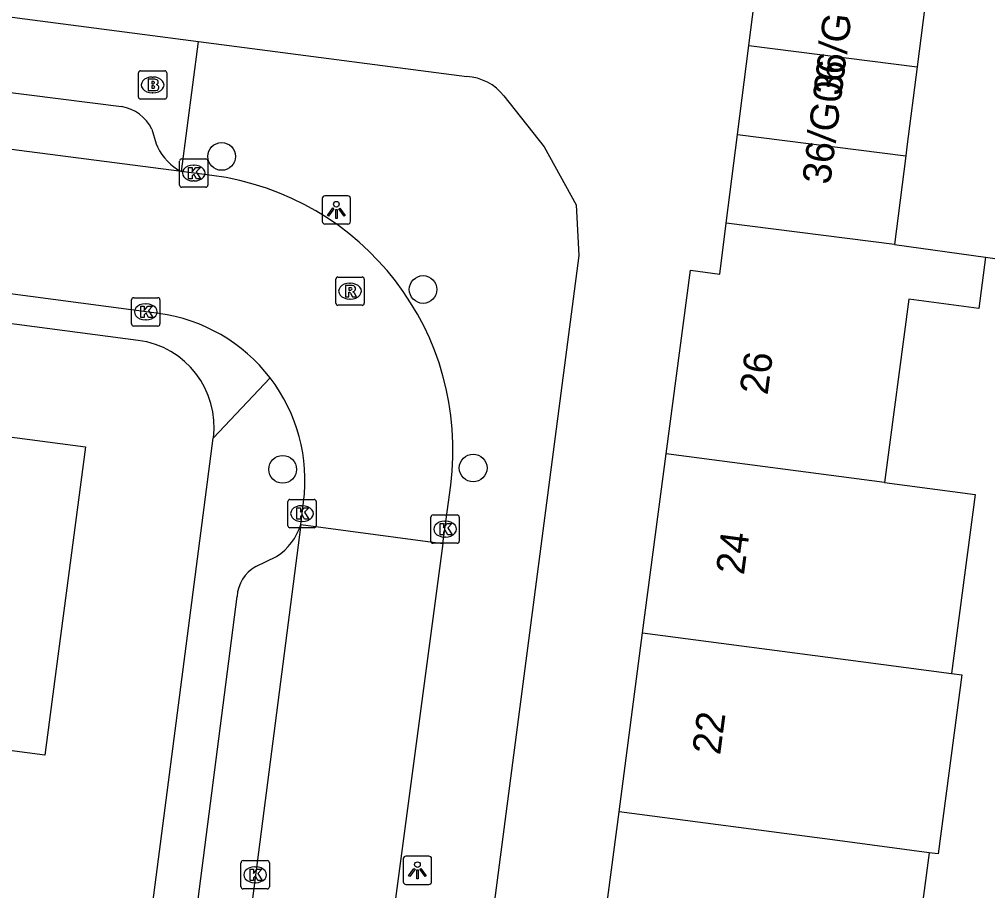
# Model space of a CAD drawing. Extents: x 162186 to 163152, y 385513 to 386513.
# Drawn here: x 162510.63 to 162544.83, y 386223.73 to 386254.5 of the extents above; entities that cross this region are included whole.
import ezdxf

# ---------------------------------------------------------------- set-up
doc = ezdxf.new("R2010")
doc.units = 0
for name, color, linetype in [('IMGEO_Boom', 7, 'Continuous'), ('IMGEO_Brandkraan', 7, 'Continuous'), ('IMGEO_Kolk', 7, 'Continuous'), ('IMGEO_Lichtpunt', 7, 'Continuous'), ('IMGEO_Muur', 7, 'Continuous'), ('IMGEO_Pand', 7, 'Continuous'), ('IMGEO_Pand_nummerreeks', 7, 'Continuous'), ('IMGEO_Rijbaan_lokaal_open', 7, 'Continuous'), ('IMGEO_Rioolput', 7, 'Continuous'), ('IMGEO_Voetpad_open', 7, 'Continuous')]:
    doc.layers.add(name, color=color, linetype=linetype)

msp = doc.modelspace()

# ---------------------------------------------------------------- linework, layer by layer
at = {"layer": 'IMGEO_Boom'}
for centre in [(162517.778, 386249.657), (162524.891, 386244.959), (162519.931, 386238.608), (162526.659, 386238.655)]:
    msp.add_circle(centre, 0.489, dxfattribs=at)
at = {"layer": 'IMGEO_Brandkraan'}
for p, q in [((162514.914, 386252.681), (162515.766, 386252.681)), ((162514.839, 386251.755), (162514.839, 386252.607)), ((162515.327, 386252.461), (162515.352, 386252.461)), ((162515.84, 386252.607), (162515.84, 386251.755)), ((162515.766, 386251.681), (162514.914, 386251.681)), ((162515.35, 386251.901), (162515.325, 386251.901))]:
    msp.add_line(p, q, dxfattribs=at)
for points in [[(162514.914, 386252.681), (162515.766, 386252.681)], [(162514.839, 386251.755), (162514.839, 386252.607)], [(162515.187, 386252.381), (162515.187, 386251.981), (162515.4, 386251.981)], [(162515.418, 386252.381), (162515.187, 386252.381)], [(162515.84, 386252.607), (162515.84, 386251.755)], [(162515.366, 386252.3), (162515.312, 386252.3), (162515.312, 386252.224)], [(162515.312, 386252.224), (162515.365, 386252.224)], [(162515.374, 386252.148), (162515.312, 386252.148), (162515.312, 386252.067)], [(162515.312, 386252.067), (162515.374, 386252.067)], [(162515.766, 386251.681), (162514.914, 386251.681)]]:
    msp.add_lwpolyline(points, dxfattribs=at)
for centre, radius, start, end in [((162514.916, 386252.605), 0.0765, 91.552, 178.448), ((162514.916, 386252.605), 0.0765, 91.552, 178.448), ((162515.764, 386252.605), 0.0765, 1.552, 88.448), ((162515.764, 386252.605), 0.0765, 1.552, 88.448), ((162515.422, 386252.236), 0.145, 59.4692, 91.5367), ((162515.447, 386252.283), 0.0922, 285.5137, 58.1501), ((162515.367, 386252.262), 0.0379, 267.8285, 90.9355), ((162515.375, 386252.107), 0.0404, 269.8759, 90.5077), ((162515.406, 386252.232), 0.251, 268.6676, 293.5347), ((162515.452, 386252.091), 0.105, 301.3115, 78.989), ((162514.916, 386251.757), 0.0765, 181.552, 268.448), ((162514.916, 386251.757), 0.0765, 181.552, 268.448), ((162515.764, 386251.757), 0.0765, 271.552, 358.448), ((162515.764, 386251.757), 0.0765, 271.552, 358.448)]:
    msp.add_arc(centre, radius, start, end, dxfattribs=at)
for centre, major_axis, ratio, start_param, end_param in [((162515.326, 386252.181), (-0.387, 0.002), 0.722429, 4.712389, 7.853982), ((162515.351, 386252.181), (-0.39, 0.002), 0.717154, 1.570796, 4.712389)]:
    msp.add_ellipse(centre, major_axis=major_axis, ratio=ratio, start_param=start_param, end_param=end_param, dxfattribs=at)
at = {"layer": 'IMGEO_Kolk'}
for p, q in [((162516.29, 386248.644), (162516.29, 386249.496)), ((162516.365, 386249.57), (162517.217, 386249.57)), ((162516.778, 386249.35), (162516.803, 386249.35)), ((162517.291, 386249.496), (162517.291, 386248.644)), ((162517.217, 386248.57), (162516.365, 386248.57)), ((162516.801, 386248.79), (162516.776, 386248.79)), ((162514.598, 386243.743), (162514.598, 386244.595)), ((162514.673, 386244.669), (162515.525, 386244.669)), ((162515.599, 386244.595), (162515.599, 386243.743)), ((162515.086, 386244.449), (162515.111, 386244.449)), ((162515.109, 386243.889), (162515.084, 386243.889)), ((162515.525, 386243.669), (162514.673, 386243.669)), ((162520.114, 386236.619), (162520.114, 386237.471)), ((162520.189, 386237.545), (162521.041, 386237.545)), ((162520.602, 386237.325), (162520.627, 386237.325)), ((162521.115, 386237.471), (162521.115, 386236.619)), ((162525.243, 386236.997), (162526.095, 386236.997)), ((162520.625, 386236.765), (162520.6, 386236.765)), ((162525.168, 386236.071), (162525.168, 386236.923)), ((162525.656, 386236.777), (162525.681, 386236.777)), ((162526.169, 386236.923), (162526.169, 386236.071)), ((162521.041, 386236.545), (162520.189, 386236.545)), ((162526.095, 386235.997), (162525.243, 386235.997)), ((162525.679, 386236.217), (162525.654, 386236.217)), ((162518.46, 386223.868), (162518.46, 386224.72)), ((162518.535, 386224.794), (162519.387, 386224.794)), ((162519.461, 386224.72), (162519.461, 386223.868)), ((162518.948, 386224.574), (162518.973, 386224.574)), ((162518.971, 386224.014), (162518.946, 386224.014)), ((162519.387, 386223.794), (162518.535, 386223.794))]:
    msp.add_line(p, q, dxfattribs=at)
for points in [[(162516.29, 386248.644), (162516.29, 386249.496)], [(162516.365, 386249.57), (162517.217, 386249.57)], [(162516.611, 386249.27), (162516.734, 386249.27), (162516.734, 386249.119), (162516.864, 386249.27), (162517.028, 386249.27), (162516.882, 386249.119), (162517.035, 386248.87), (162516.883, 386248.87), (162516.798, 386249.034), (162516.734, 386248.967), (162516.734, 386248.87), (162516.611, 386248.87), (162516.611, 386249.27)], [(162517.291, 386249.496), (162517.291, 386248.644)], [(162517.217, 386248.57), (162516.365, 386248.57)], [(162514.598, 386243.743), (162514.598, 386244.595)], [(162514.673, 386244.669), (162515.525, 386244.669)], [(162515.599, 386244.595), (162515.599, 386243.743)], [(162514.919, 386244.369), (162515.042, 386244.369), (162515.042, 386244.218), (162515.172, 386244.369), (162515.336, 386244.369), (162515.19, 386244.218), (162515.343, 386243.969), (162515.191, 386243.969), (162515.106, 386244.133), (162515.042, 386244.066), (162515.042, 386243.969), (162514.919, 386243.969), (162514.919, 386244.369)], [(162515.525, 386243.669), (162514.673, 386243.669)], [(162520.114, 386236.619), (162520.114, 386237.471)], [(162520.189, 386237.545), (162521.041, 386237.545)], [(162521.115, 386237.471), (162521.115, 386236.619)], [(162520.435, 386237.245), (162520.558, 386237.245), (162520.558, 386237.094), (162520.688, 386237.245), (162520.852, 386237.245), (162520.706, 386237.094), (162520.859, 386236.845), (162520.707, 386236.845), (162520.622, 386237.009), (162520.558, 386236.942), (162520.558, 386236.845), (162520.435, 386236.845), (162520.435, 386237.245)], [(162525.243, 386236.997), (162526.095, 386236.997)], [(162525.168, 386236.071), (162525.168, 386236.923)], [(162525.489, 386236.697), (162525.612, 386236.697), (162525.612, 386236.546), (162525.742, 386236.697), (162525.906, 386236.697), (162525.76, 386236.546), (162525.913, 386236.297), (162525.761, 386236.297), (162525.676, 386236.461), (162525.612, 386236.394), (162525.612, 386236.297), (162525.489, 386236.297), (162525.489, 386236.697)], [(162526.169, 386236.923), (162526.169, 386236.071)], [(162521.041, 386236.545), (162520.189, 386236.545)], [(162526.095, 386235.997), (162525.243, 386235.997)], [(162518.46, 386223.868), (162518.46, 386224.72)], [(162518.535, 386224.794), (162519.387, 386224.794)], [(162519.461, 386224.72), (162519.461, 386223.868)], [(162518.781, 386224.494), (162518.904, 386224.494), (162518.904, 386224.343), (162519.034, 386224.494), (162519.198, 386224.494), (162519.052, 386224.343), (162519.205, 386224.094), (162519.053, 386224.094), (162518.968, 386224.258), (162518.904, 386224.191), (162518.904, 386224.094), (162518.781, 386224.094), (162518.781, 386224.494)], [(162519.387, 386223.794), (162518.535, 386223.794)]]:
    msp.add_lwpolyline(points, dxfattribs=at)
for centre, start, end in [((162516.367, 386249.494), 91.552, 178.448), ((162516.367, 386249.494), 91.552, 178.448), ((162517.215, 386249.494), 1.552, 88.448), ((162517.215, 386249.494), 1.552, 88.448), ((162516.367, 386248.646), 181.552, 268.448), ((162516.367, 386248.646), 181.552, 268.448), ((162517.215, 386248.646), 271.552, 358.448), ((162517.215, 386248.646), 271.552, 358.448), ((162514.675, 386244.593), 91.552, 178.448), ((162514.675, 386244.593), 91.552, 178.448), ((162515.523, 386244.593), 1.552, 88.448), ((162515.523, 386244.593), 1.552, 88.448), ((162514.675, 386243.745), 181.552, 268.448), ((162514.675, 386243.745), 181.552, 268.448), ((162515.523, 386243.745), 271.552, 358.448), ((162515.523, 386243.745), 271.552, 358.448), ((162520.191, 386237.469), 91.552, 178.448), ((162520.191, 386237.469), 91.552, 178.448), ((162521.039, 386237.469), 1.552, 88.448), ((162521.039, 386237.469), 1.552, 88.448), ((162525.245, 386236.921), 91.552, 178.448), ((162525.245, 386236.921), 91.552, 178.448), ((162526.093, 386236.921), 1.552, 88.448), ((162526.093, 386236.921), 1.552, 88.448), ((162520.191, 386236.621), 181.552, 268.448), ((162520.191, 386236.621), 181.552, 268.448), ((162521.039, 386236.621), 271.552, 358.448), ((162521.039, 386236.621), 271.552, 358.448), ((162525.245, 386236.073), 181.552, 268.448), ((162525.245, 386236.073), 181.552, 268.448), ((162526.093, 386236.073), 271.552, 358.448), ((162526.093, 386236.073), 271.552, 358.448), ((162518.537, 386224.718), 91.552, 178.448), ((162518.537, 386224.718), 91.552, 178.448), ((162519.385, 386224.718), 1.552, 88.448), ((162519.385, 386224.718), 1.552, 88.448), ((162518.537, 386223.87), 181.552, 268.448), ((162518.537, 386223.87), 181.552, 268.448), ((162519.385, 386223.87), 271.552, 358.448), ((162519.385, 386223.87), 271.552, 358.448)]:
    msp.add_arc(centre, 0.0765, start, end, dxfattribs=at)
for centre, major_axis, ratio, start_param, end_param in [((162516.777, 386249.07), (-0.387, 0.002), 0.722429, 4.712389, 7.853982), ((162516.802, 386249.07), (-0.39, 0.002), 0.717154, 1.570796, 4.712389), ((162515.085, 386244.169), (-0.387, 0.002), 0.722429, 4.712389, 7.853982), ((162515.11, 386244.169), (-0.39, 0.002), 0.717154, 1.570796, 4.712389), ((162520.601, 386237.045), (-0.387, 0.002), 0.722429, 4.712389, 7.853982), ((162520.626, 386237.045), (-0.39, 0.002), 0.717154, 1.570796, 4.712389), ((162525.655, 386236.497), (-0.387, 0.002), 0.722429, 4.712389, 7.853982), ((162525.68, 386236.497), (-0.39, 0.002), 0.717154, 1.570796, 4.712389), ((162518.947, 386224.294), (-0.387, 0.002), 0.722429, 4.712389, 7.853982), ((162518.972, 386224.294), (-0.39, 0.002), 0.717154, 1.570796, 4.712389)]:
    msp.add_ellipse(centre, major_axis=major_axis, ratio=ratio, start_param=start_param, end_param=end_param, dxfattribs=at)
at = {"layer": 'IMGEO_Lichtpunt'}
for p, q in [((162522.232, 386248.268), (162521.424, 386248.268)), ((162522.232, 386248.268), (162521.424, 386248.268)), ((162521.33, 386248.173), (162521.33, 386247.366)), ((162521.33, 386248.173), (162521.33, 386247.366)), ((162522.326, 386247.366), (162522.326, 386248.173)), ((162522.326, 386247.366), (162522.326, 386248.173)), ((162521.424, 386247.272), (162522.232, 386247.272)), ((162521.424, 386247.272), (162522.232, 386247.272)), ((162524.193, 386224.855), (162524.193, 386224.048)), ((162524.193, 386224.855), (162524.193, 386224.048)), ((162525.095, 386224.95), (162524.287, 386224.95)), ((162525.095, 386224.95), (162524.287, 386224.95)), ((162525.189, 386224.048), (162525.189, 386224.855)), ((162525.189, 386224.048), (162525.189, 386224.855)), ((162524.287, 386223.954), (162525.095, 386223.954)), ((162524.287, 386223.954), (162525.095, 386223.954))]:
    msp.add_line(p, q, dxfattribs=at)
for points in [[(162521.704, 386247.837), (162521.743, 386247.809), (162521.555, 386247.547), (162521.517, 386247.574), (162521.704, 386247.837)], [(162521.806, 386247.789), (162521.853, 386247.789), (162521.853, 386247.467), (162521.806, 386247.467), (162521.806, 386247.789)], [(162521.916, 386247.809), (162521.954, 386247.836), (162522.141, 386247.574), (162522.102, 386247.546), (162521.916, 386247.809)], [(162524.567, 386224.519), (162524.606, 386224.491), (162524.418, 386224.229), (162524.38, 386224.256), (162524.567, 386224.519)], [(162524.669, 386224.471), (162524.716, 386224.471), (162524.716, 386224.149), (162524.669, 386224.149), (162524.669, 386224.471)], [(162524.779, 386224.491), (162524.817, 386224.518), (162525.004, 386224.256), (162524.965, 386224.228), (162524.779, 386224.491)]]:
    msp.add_lwpolyline(points, dxfattribs=at)
for centre in [(162521.829, 386247.971), (162524.692, 386224.653)]:
    msp.add_circle(centre, 0.0994, dxfattribs=at)
for centre, start, end in [((162521.424, 386248.173), 90, 180), ((162521.424, 386248.173), 90, 180), ((162522.232, 386248.173), 0, 90), ((162522.232, 386248.173), 0, 90), ((162521.424, 386247.366), 180, 270), ((162521.424, 386247.366), 180, 270), ((162522.232, 386247.366), 270, 0), ((162522.232, 386247.366), 270, 360), ((162524.287, 386224.855), 90, 180), ((162524.287, 386224.855), 90, 180), ((162525.095, 386224.855), 0, 90), ((162525.095, 386224.855), 0, 90), ((162524.287, 386224.048), 180, 270), ((162524.287, 386224.048), 180, 270), ((162525.095, 386224.048), 270, 0), ((162525.095, 386224.048), 270, 360)]:
    msp.add_arc(centre, 0.0946, start, end, dxfattribs=at)
at = {"layer": 'IMGEO_Muur'}
msp.add_lwpolyline([(162544.758, 386246.095), (162549.689, 386245.409)], dxfattribs=at)
at = {"layer": 'IMGEO_Pand'}
for points in [[(162542.737, 386255.958), (162542.338, 386252.819)], [(162536.392, 386253.575), (162536.591, 386255.142)], [(162535.993, 386250.436), (162536.392, 386253.575)], [(162536.392, 386253.575), (162542.338, 386252.819)], [(162542.338, 386252.819), (162541.98, 386250), (162541.939, 386249.681)], [(162535.595, 386247.298), (162535.993, 386250.436)], [(162535.993, 386250.436), (162541.939, 386249.681)], [(162541.939, 386249.681), (162541.541, 386246.543)], [(162533.477, 386239.162), (162534.331, 386245.637), (162535.367, 386245.5), (162535.595, 386247.298)], [(162541.541, 386246.543), (162535.595, 386247.298)], [(162541.541, 386246.543), (162544.758, 386246.095)], [(162544.758, 386246.095), (162544.521, 386244.293), (162542.042, 386244.62), (162541.188, 386238.144)], [(162506.338, 386240.28), (162512.974, 386239.402), (162511.938, 386231.567), (162511.535, 386228.516), (162507.152, 386229.096), (162507.555, 386232.147), (162506.982, 386232.223), (162505.316, 386232.444)], [(162532.644, 386232.841), (162533.477, 386239.162)], [(162541.188, 386238.144), (162533.477, 386239.162)], [(162541.188, 386238.144), (162544.39, 386237.72), (162543.557, 386231.4)], [(162531.811, 386226.521), (162532.644, 386232.841)], [(162532.644, 386232.841), (162540.355, 386231.822), (162543.557, 386231.4)], [(162543.557, 386231.4), (162543.913, 386231.353), (162543.08, 386225.032), (162542.761, 386225.074)], [(162530.978, 386220.201), (162531.811, 386226.521)], [(162542.761, 386225.074), (162539.522, 386225.502), (162531.811, 386226.521)], [(162542.761, 386225.074), (162542.409, 386222.412), (162539.171, 386222.84), (162538.688, 386219.182)]]:
    msp.add_lwpolyline(points, dxfattribs=at)
at = {"layer": 'IMGEO_Rijbaan_lokaal_open'}
for points in [[(162516.358, 386249.125), (162509.618, 386250), (162500, 386251.249), (162452.282, 386257.493)], [(162515.557, 386244.109), (162500, 386246.174), (162474.386, 386249.54)], [(162517.434, 386248.985), (162516.358, 386249.125)], [(162544.758, 386246.095), (162549.689, 386245.409)], [(162525.592, 386235.986), (162525.867, 386238.045)], [(162520.569, 386236.666), (162520.67, 386237.453)], [(162520.569, 386236.666), (162514.746, 386191.574)], [(162520.569, 386236.666), (162525.592, 386235.986)], [(162525.592, 386235.986), (162519.686, 386191.776), (162519.542, 386190.566)]]:
    msp.add_lwpolyline(points, dxfattribs=at)
for centre, radius, start, end in [((162516.177, 386239.296), 9.77, 352.6451, 82.6079), ((162514.776, 386238.217), 5.944, 37.5352, 82.446), ((162514.779, 386238.218), 5.941, 352.602, 37.5453)]:
    msp.add_arc(centre, radius, start, end, dxfattribs=at)
at = {"layer": 'IMGEO_Rioolput'}
for p, q in [((162521.809, 386244.474), (162521.809, 386245.326)), ((162521.884, 386245.4), (162522.736, 386245.4)), ((162522.297, 386245.18), (162522.322, 386245.18)), ((162522.81, 386245.326), (162522.81, 386244.474)), ((162522.32, 386244.62), (162522.295, 386244.62)), ((162522.736, 386244.4), (162521.884, 386244.4))]:
    msp.add_line(p, q, dxfattribs=at)
for points in [[(162521.809, 386244.474), (162521.809, 386245.326)], [(162521.884, 386245.4), (162522.736, 386245.4)], [(162522.81, 386245.326), (162522.81, 386244.474)], [(162522.398, 386245.098), (162522.146, 386245.1), (162522.146, 386244.7)], [(162522.146, 386244.7), (162522.27, 386244.7), (162522.27, 386244.862), (162522.281, 386244.862)], [(162522.324, 386245.019), (162522.27, 386245.019), (162522.27, 386244.938)], [(162522.27, 386244.938), (162522.322, 386244.938)], [(162522.328, 386244.833), (162522.399, 386244.7), (162522.539, 386244.7), (162522.474, 386244.826)], [(162522.736, 386244.4), (162521.884, 386244.4)]]:
    msp.add_lwpolyline(points, dxfattribs=at)
for centre, radius, start, end in [((162521.886, 386245.324), 0.0765, 91.552, 178.448), ((162521.886, 386245.324), 0.0765, 91.552, 178.448), ((162522.734, 386245.324), 0.0765, 1.552, 88.448), ((162522.734, 386245.324), 0.0765, 1.552, 88.448), ((162522.28, 386244.809), 0.0533, 26.0293, 88.6989), ((162522.306, 386245.127), 0.19, 274.7715, 282.9687), ((162522.33, 386244.923), 0.0964, 77.0061, 93.1865), ((162522.344, 386244.98), 0.0378, 276.6634, 79.6772), ((162522.397, 386244.988), 0.109, 350.3612, 89.416), ((162522.395, 386244.988), 0.112, 277.5842, 350.9817), ((162522.379, 386244.773), 0.108, 29.5134, 73.7905), ((162521.886, 386244.476), 0.0765, 181.552, 268.448), ((162521.886, 386244.476), 0.0765, 181.552, 268.448), ((162522.734, 386244.476), 0.0765, 271.552, 358.448), ((162522.734, 386244.476), 0.0765, 271.552, 358.448)]:
    msp.add_arc(centre, radius, start, end, dxfattribs=at)
for centre, major_axis, ratio, start_param, end_param in [((162522.296, 386244.9), (-0.387, 0.002), 0.722429, 4.712389, 7.853982), ((162522.321, 386244.9), (-0.39, 0.002), 0.717154, 1.570796, 4.712389)]:
    msp.add_ellipse(centre, major_axis=major_axis, ratio=ratio, start_param=start_param, end_param=end_param, dxfattribs=at)
at = {"layer": 'IMGEO_Voetpad_open'}
for points in [[(162407.034, 386268.116), (162500, 386255.941), (162516.96, 386253.72)], [(162477.472, 386256.096), (162482.084, 386255.488), (162514.241, 386251.416)], [(162516.358, 386249.125), (162516.96, 386253.72)], [(162516.96, 386253.72), (162526.433, 386252.479)], [(162527.746, 386251.794), (162529.167, 386250), (162530.299, 386247.954), (162530.386, 386246.165), (162518.722, 386156.946)], [(162515.315, 386250.619), (162515.46, 386250.1), (162515.506, 386249.999)], [(162514.83, 386243.164), (162500, 386245.113), (162475.169, 386248.376)], [(162517.483, 386239.714), (162519.489, 386241.838)], [(162514.479, 386216.591), (162517.483, 386239.714)], [(162518.979, 386235.177), (162519.717, 386235.535)], [(162516.6, 386220.687), (162518.321, 386234.121)]]:
    msp.add_lwpolyline(points, dxfattribs=at)
for centre, radius, start, end in [((162526.326, 386250.674), 1.808, 38.2753, 86.6221), ((162514.006, 386249.977), 1.458, 26.1121, 80.7308), ((162517.224, 386250.821), 1.905, 205.5817, 242.9578), ((162514.429, 386240.11), 3.08, 352.6085, 82.511), ((162518.626, 386237.243), 2.027, 302.5605, 343.4569), ((162519.632, 386234.037), 1.314, 119.808, 176.3374)]:
    msp.add_arc(centre, radius, start, end, dxfattribs=at)

# ---------------------------------------------------------------- texts
at = {"layer": 'IMGEO_Pand_nummerreeks'}
for s, rotation, p in [('36/G05', 82.7588, (162539.666, 386251.779)), ('36/G06', 82.7592, (162539.267, 386248.641)), ('26', 82.4898, (162537.056, 386241.212)), ('24', 82.4898, (162536.219, 386234.858)), ('22', 82.4887, (162535.38, 386228.501))]:
    msp.add_text(s, height=1, rotation=rotation, dxfattribs=at).set_placement(p)

doc.saveas('drawing.dxf')
